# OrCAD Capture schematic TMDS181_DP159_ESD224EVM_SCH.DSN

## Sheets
1 P03:  DP159RGZ: size B; title: DP159 RGZ (48-pin QFN); rev: A.0; company: Texas Instruments, CIS/ICP; note: GAGGIA.DSN
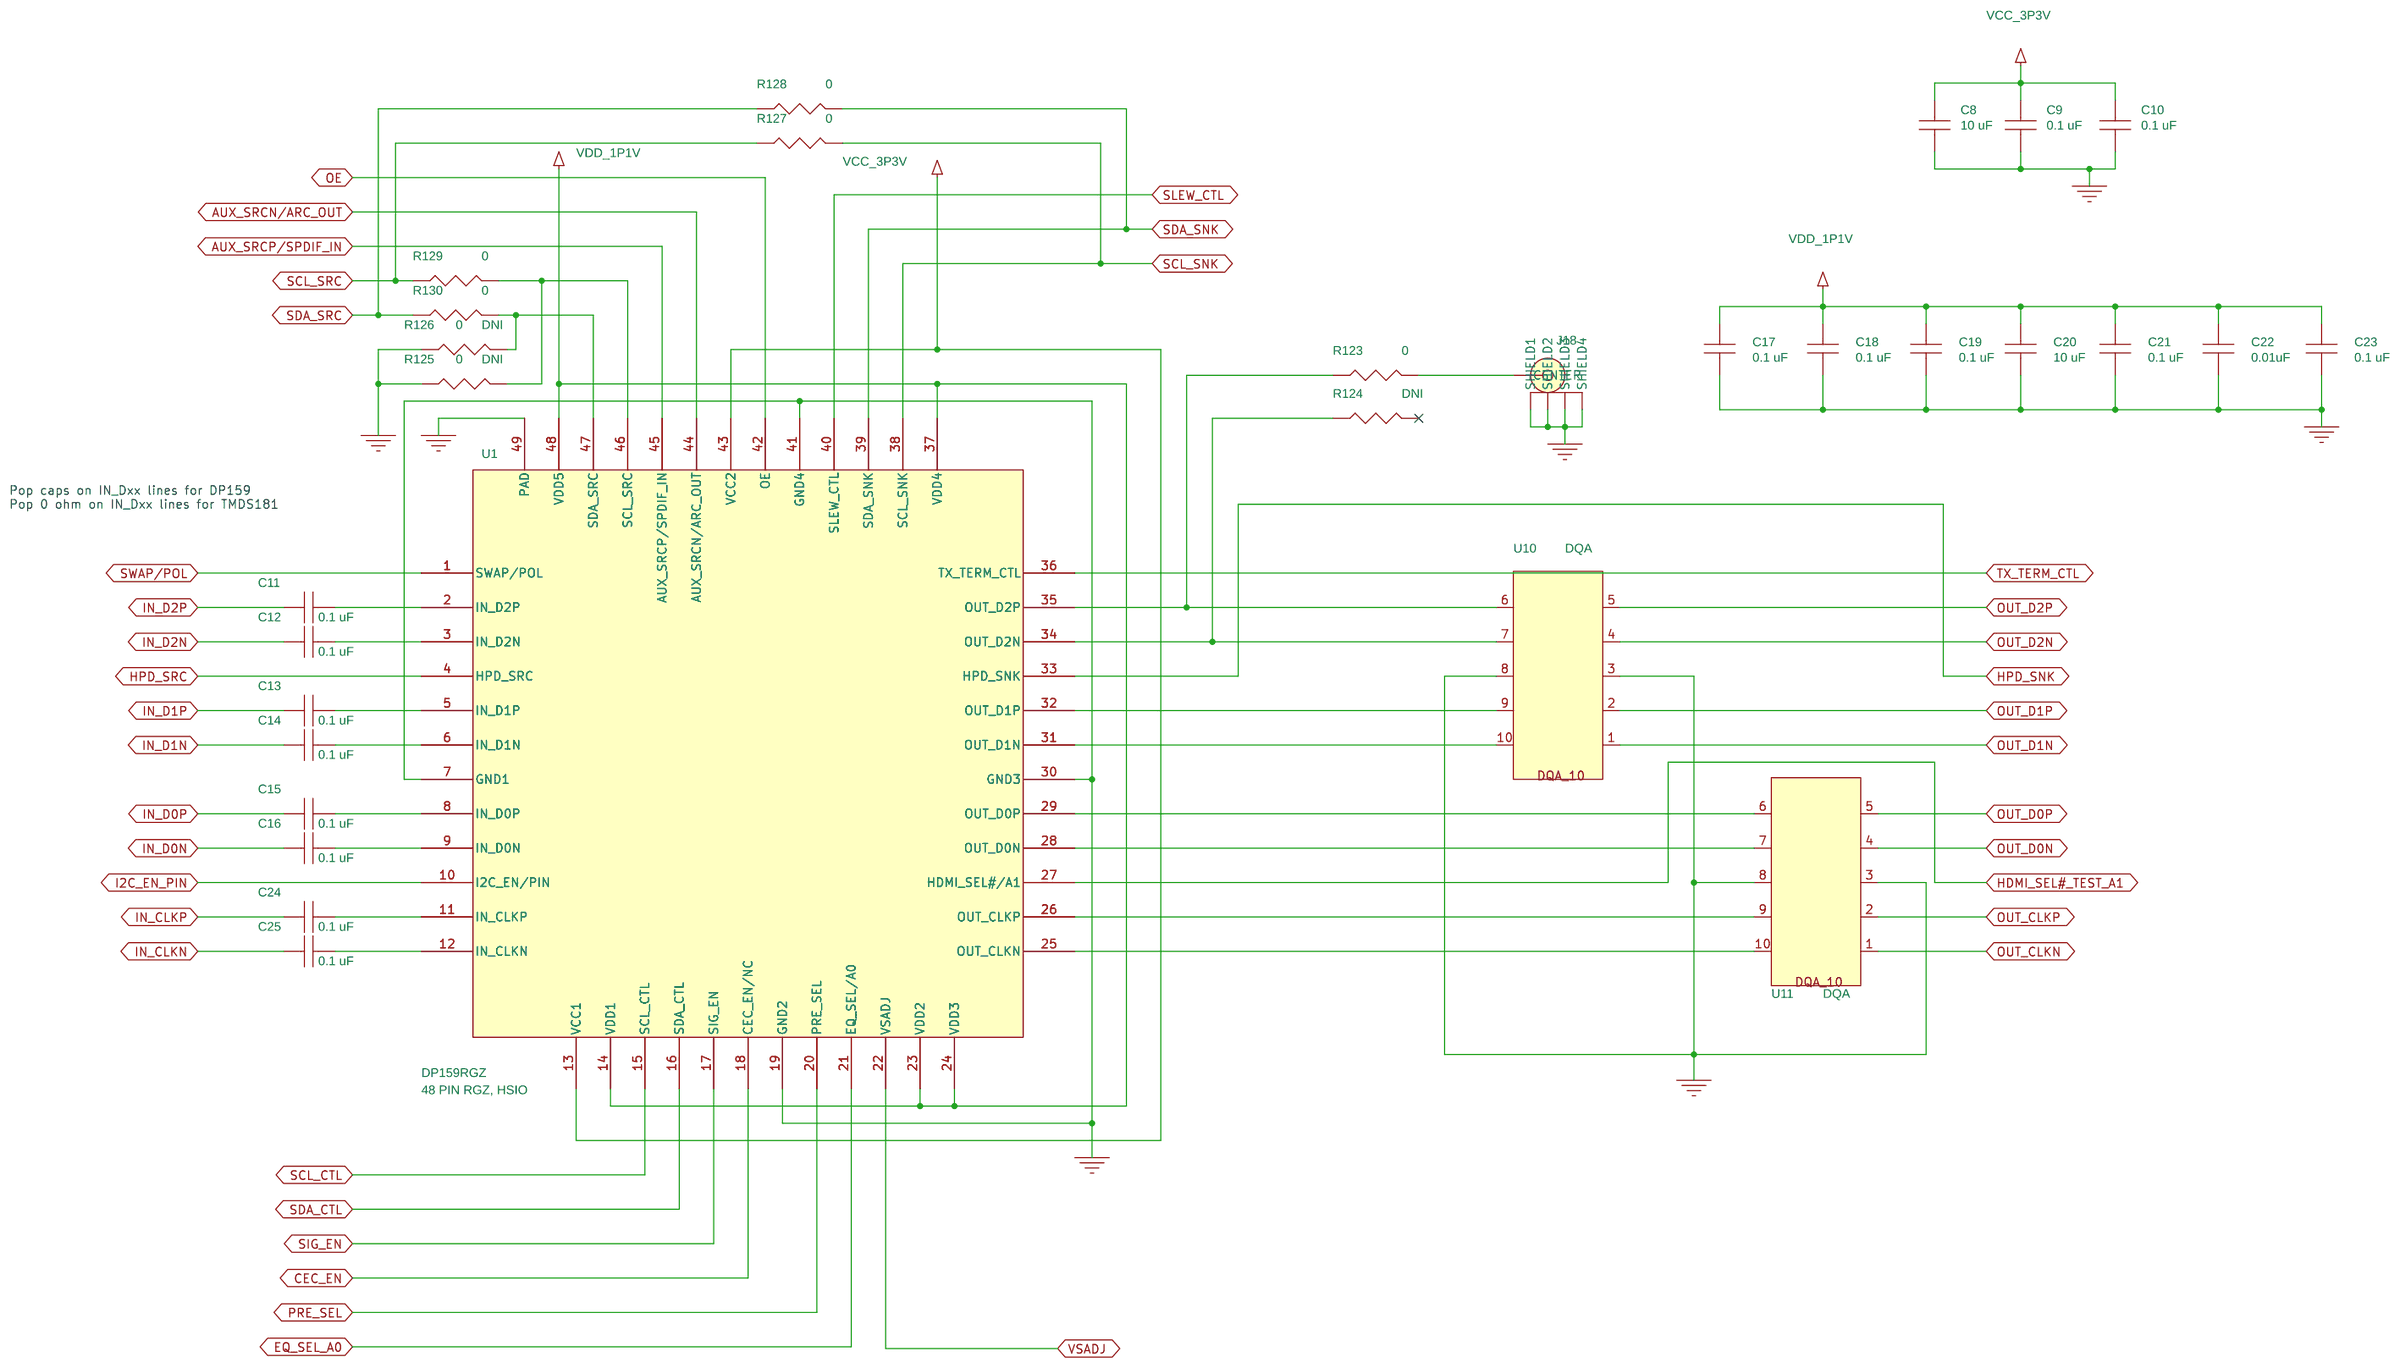
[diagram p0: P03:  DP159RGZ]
2 P06:  RESET: size A; title: RESET
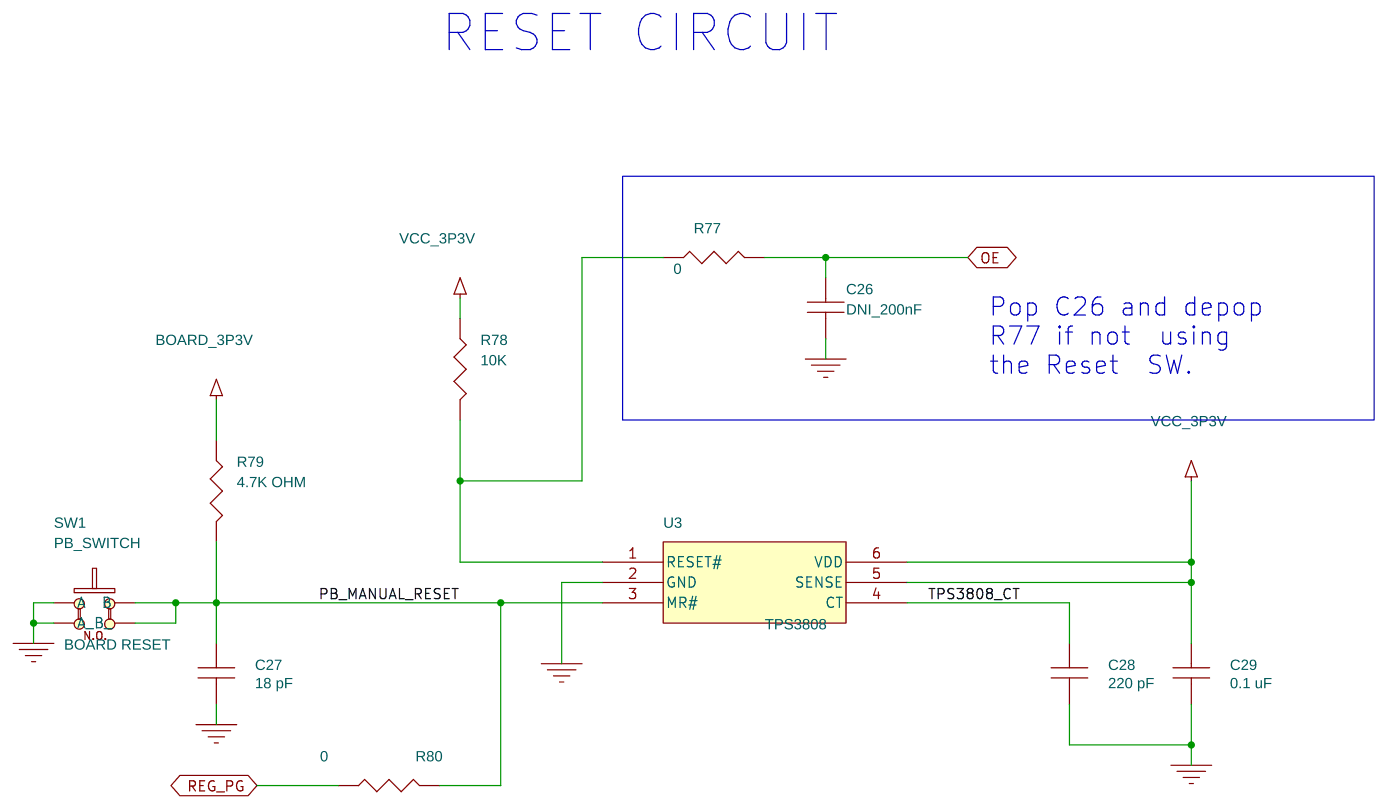
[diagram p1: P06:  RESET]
3 P01:  TITLE: size A; title: TMDS181_DP159_ESD224EVM_REVA
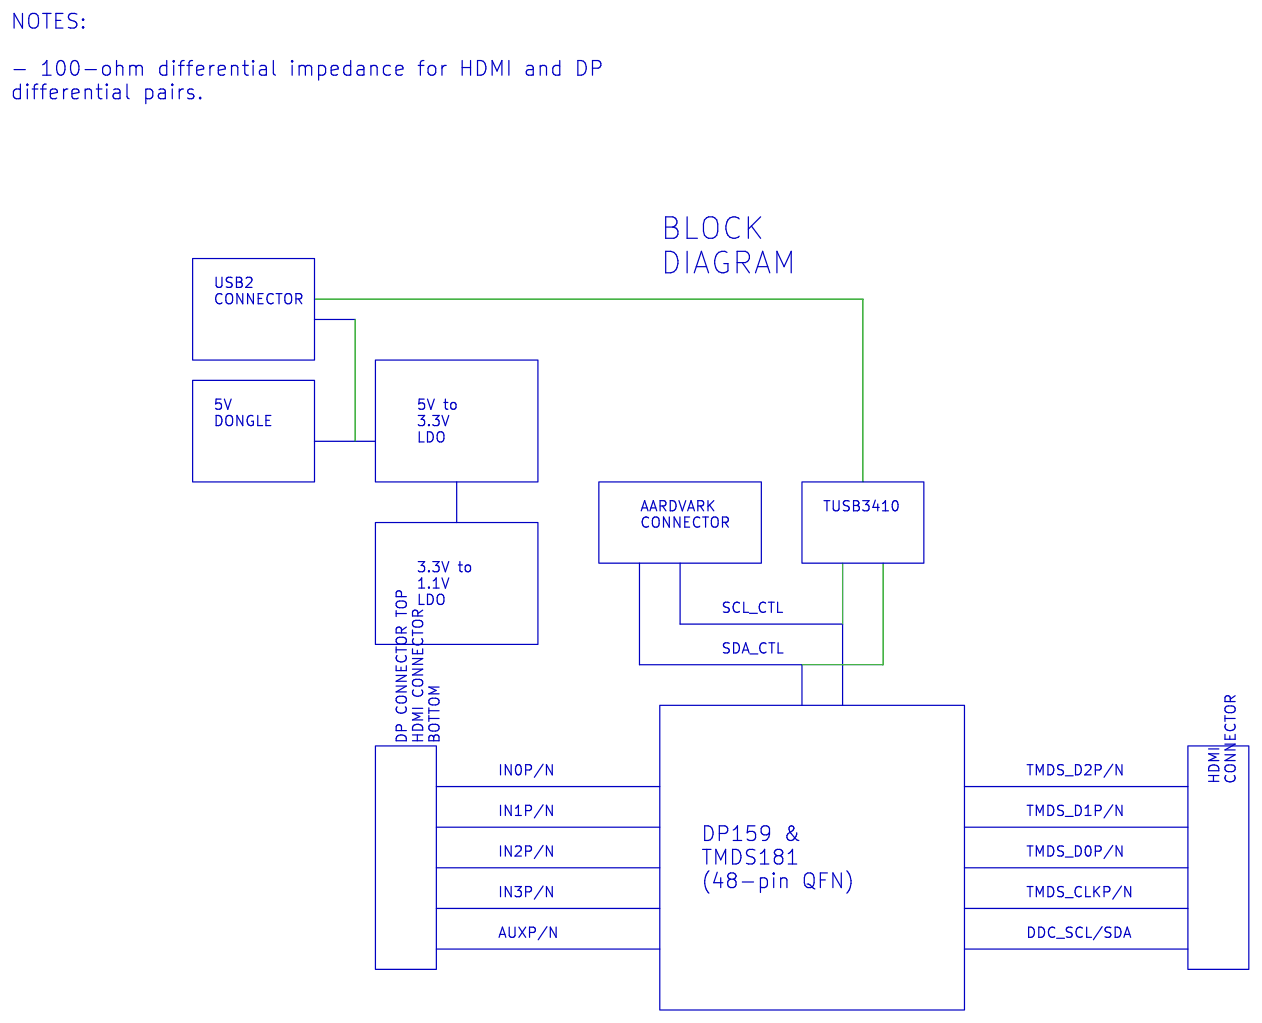
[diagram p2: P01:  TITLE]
4 P07:  POWER: size B; title: 1.1V AND 3.3V REGULATORS
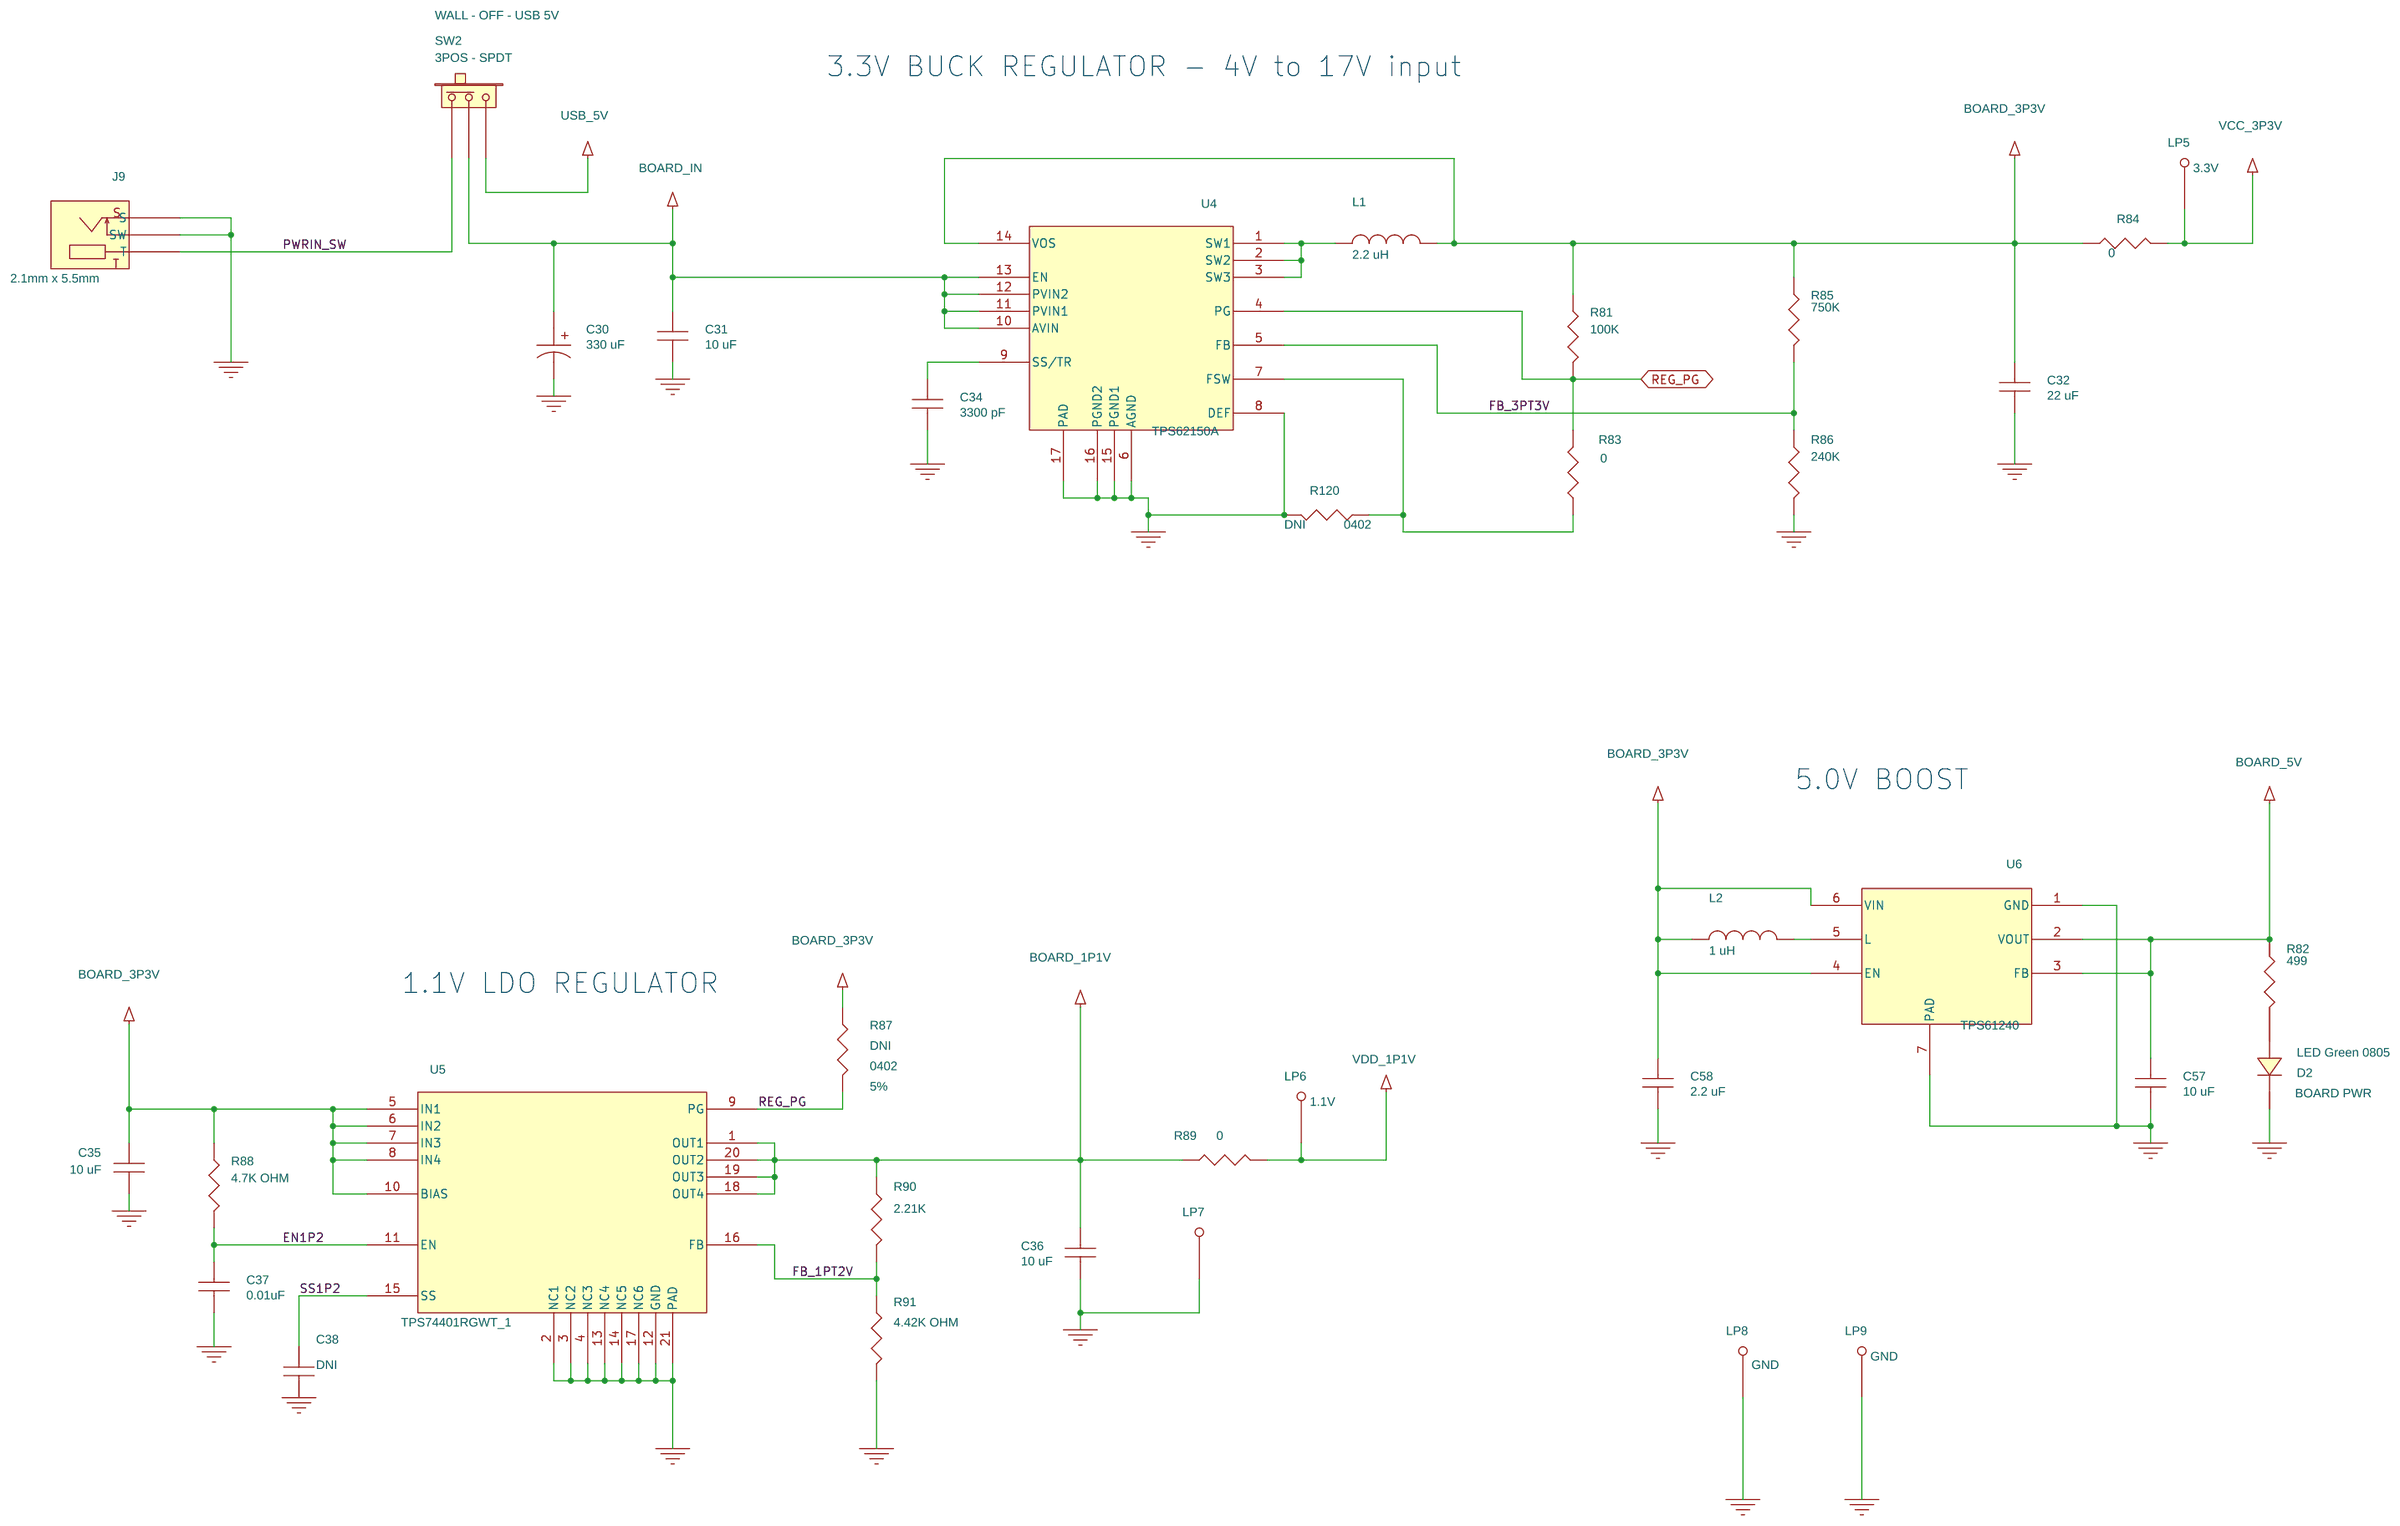
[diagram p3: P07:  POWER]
5 P04:  HDMI TX CONNECTOR: size A; title: HDMI TX CONNECTOR
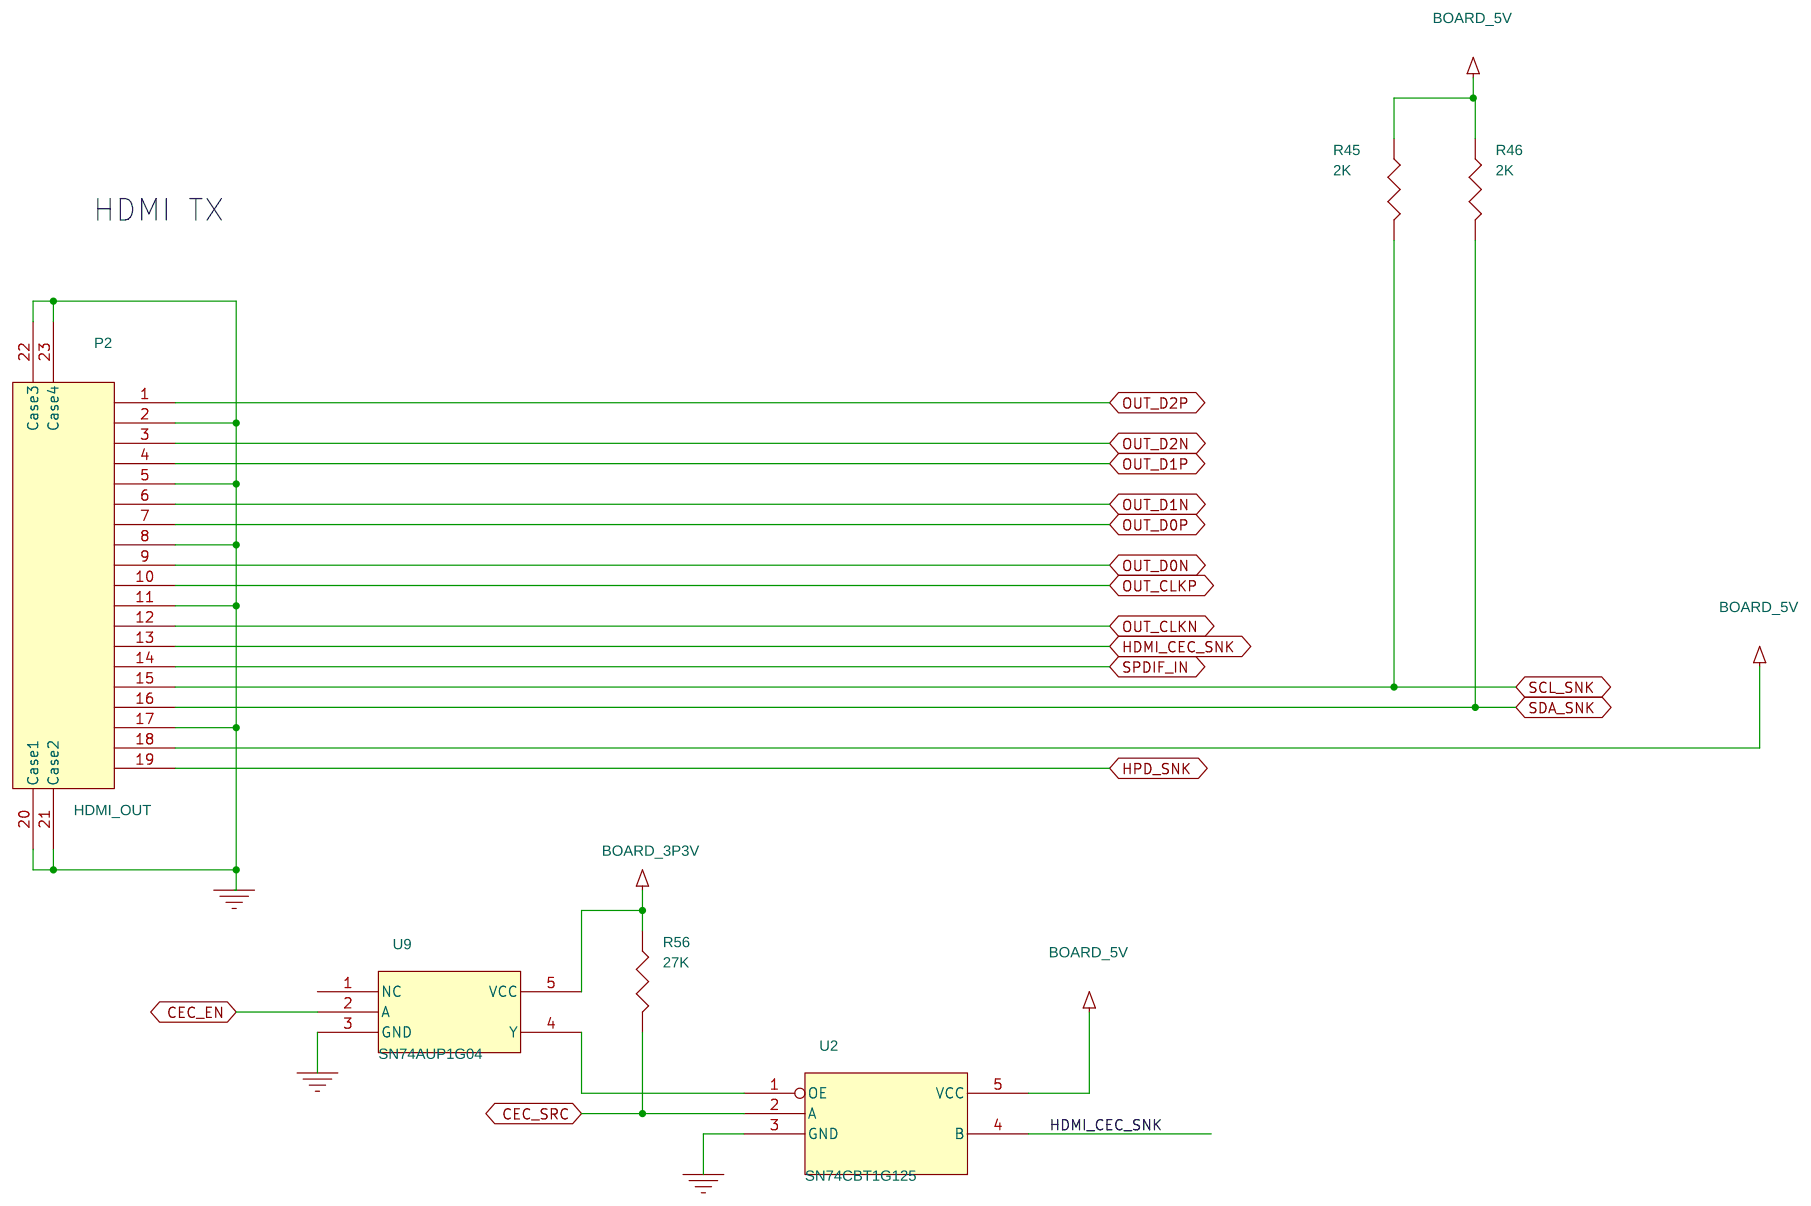
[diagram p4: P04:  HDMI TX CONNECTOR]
6 P08:  TUSB3410: size B; title: TUSB3410
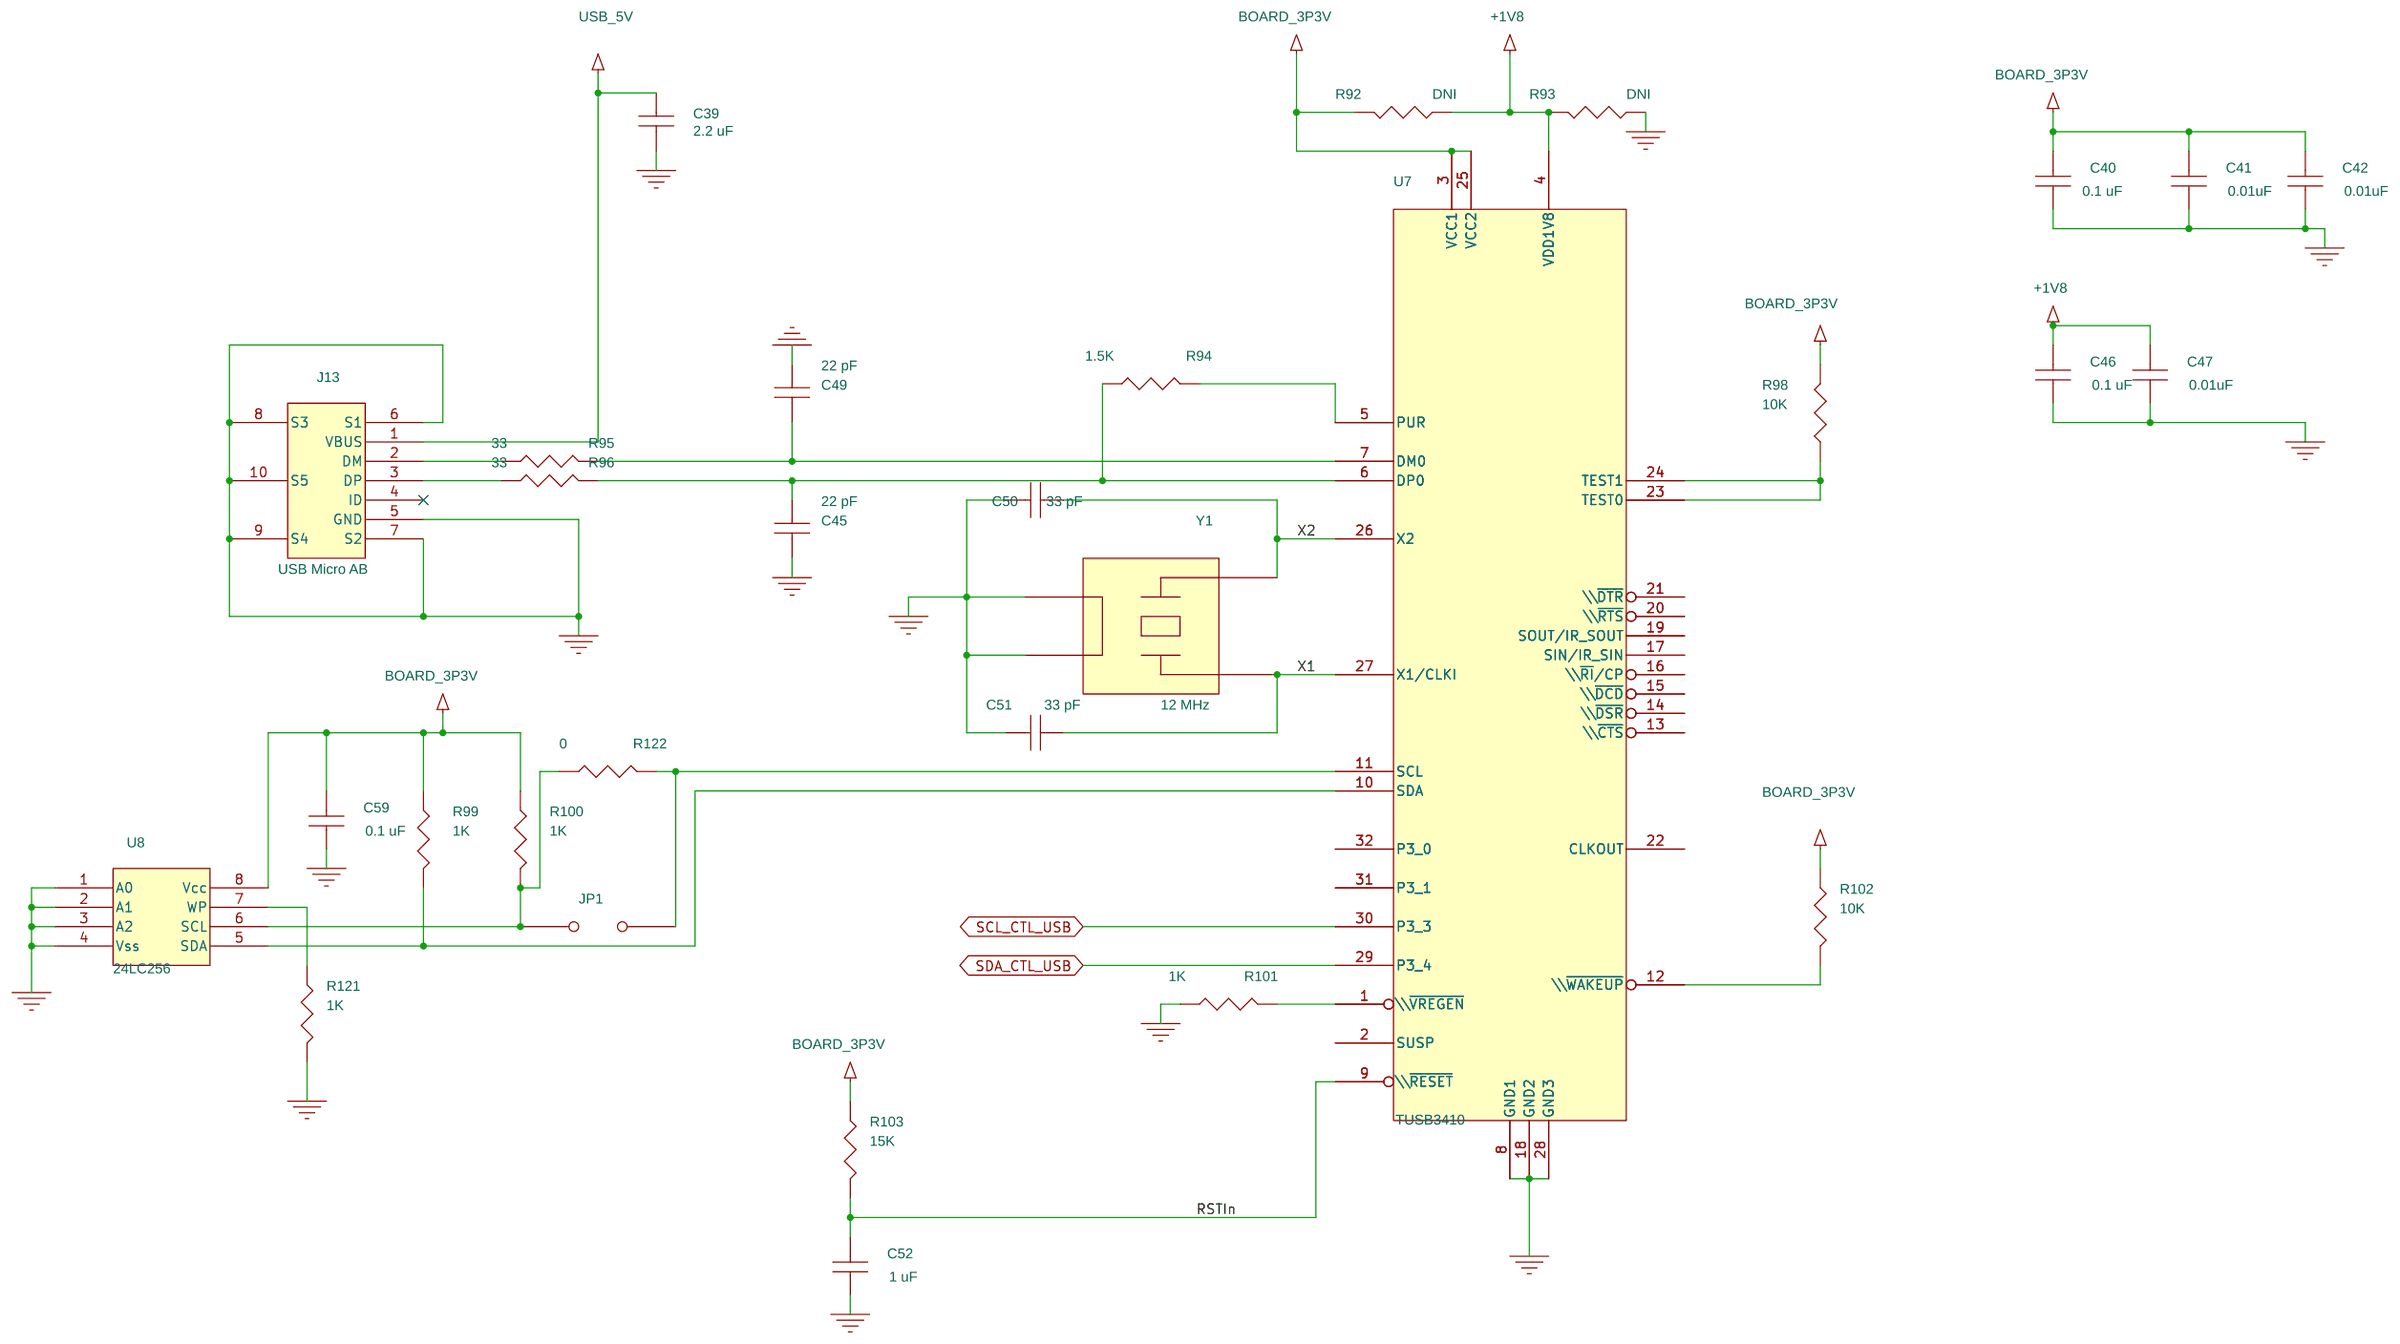
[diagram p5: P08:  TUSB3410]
7 P05:  DP159 SEL OPTIONS: size B; title: SELECT OPTIONS
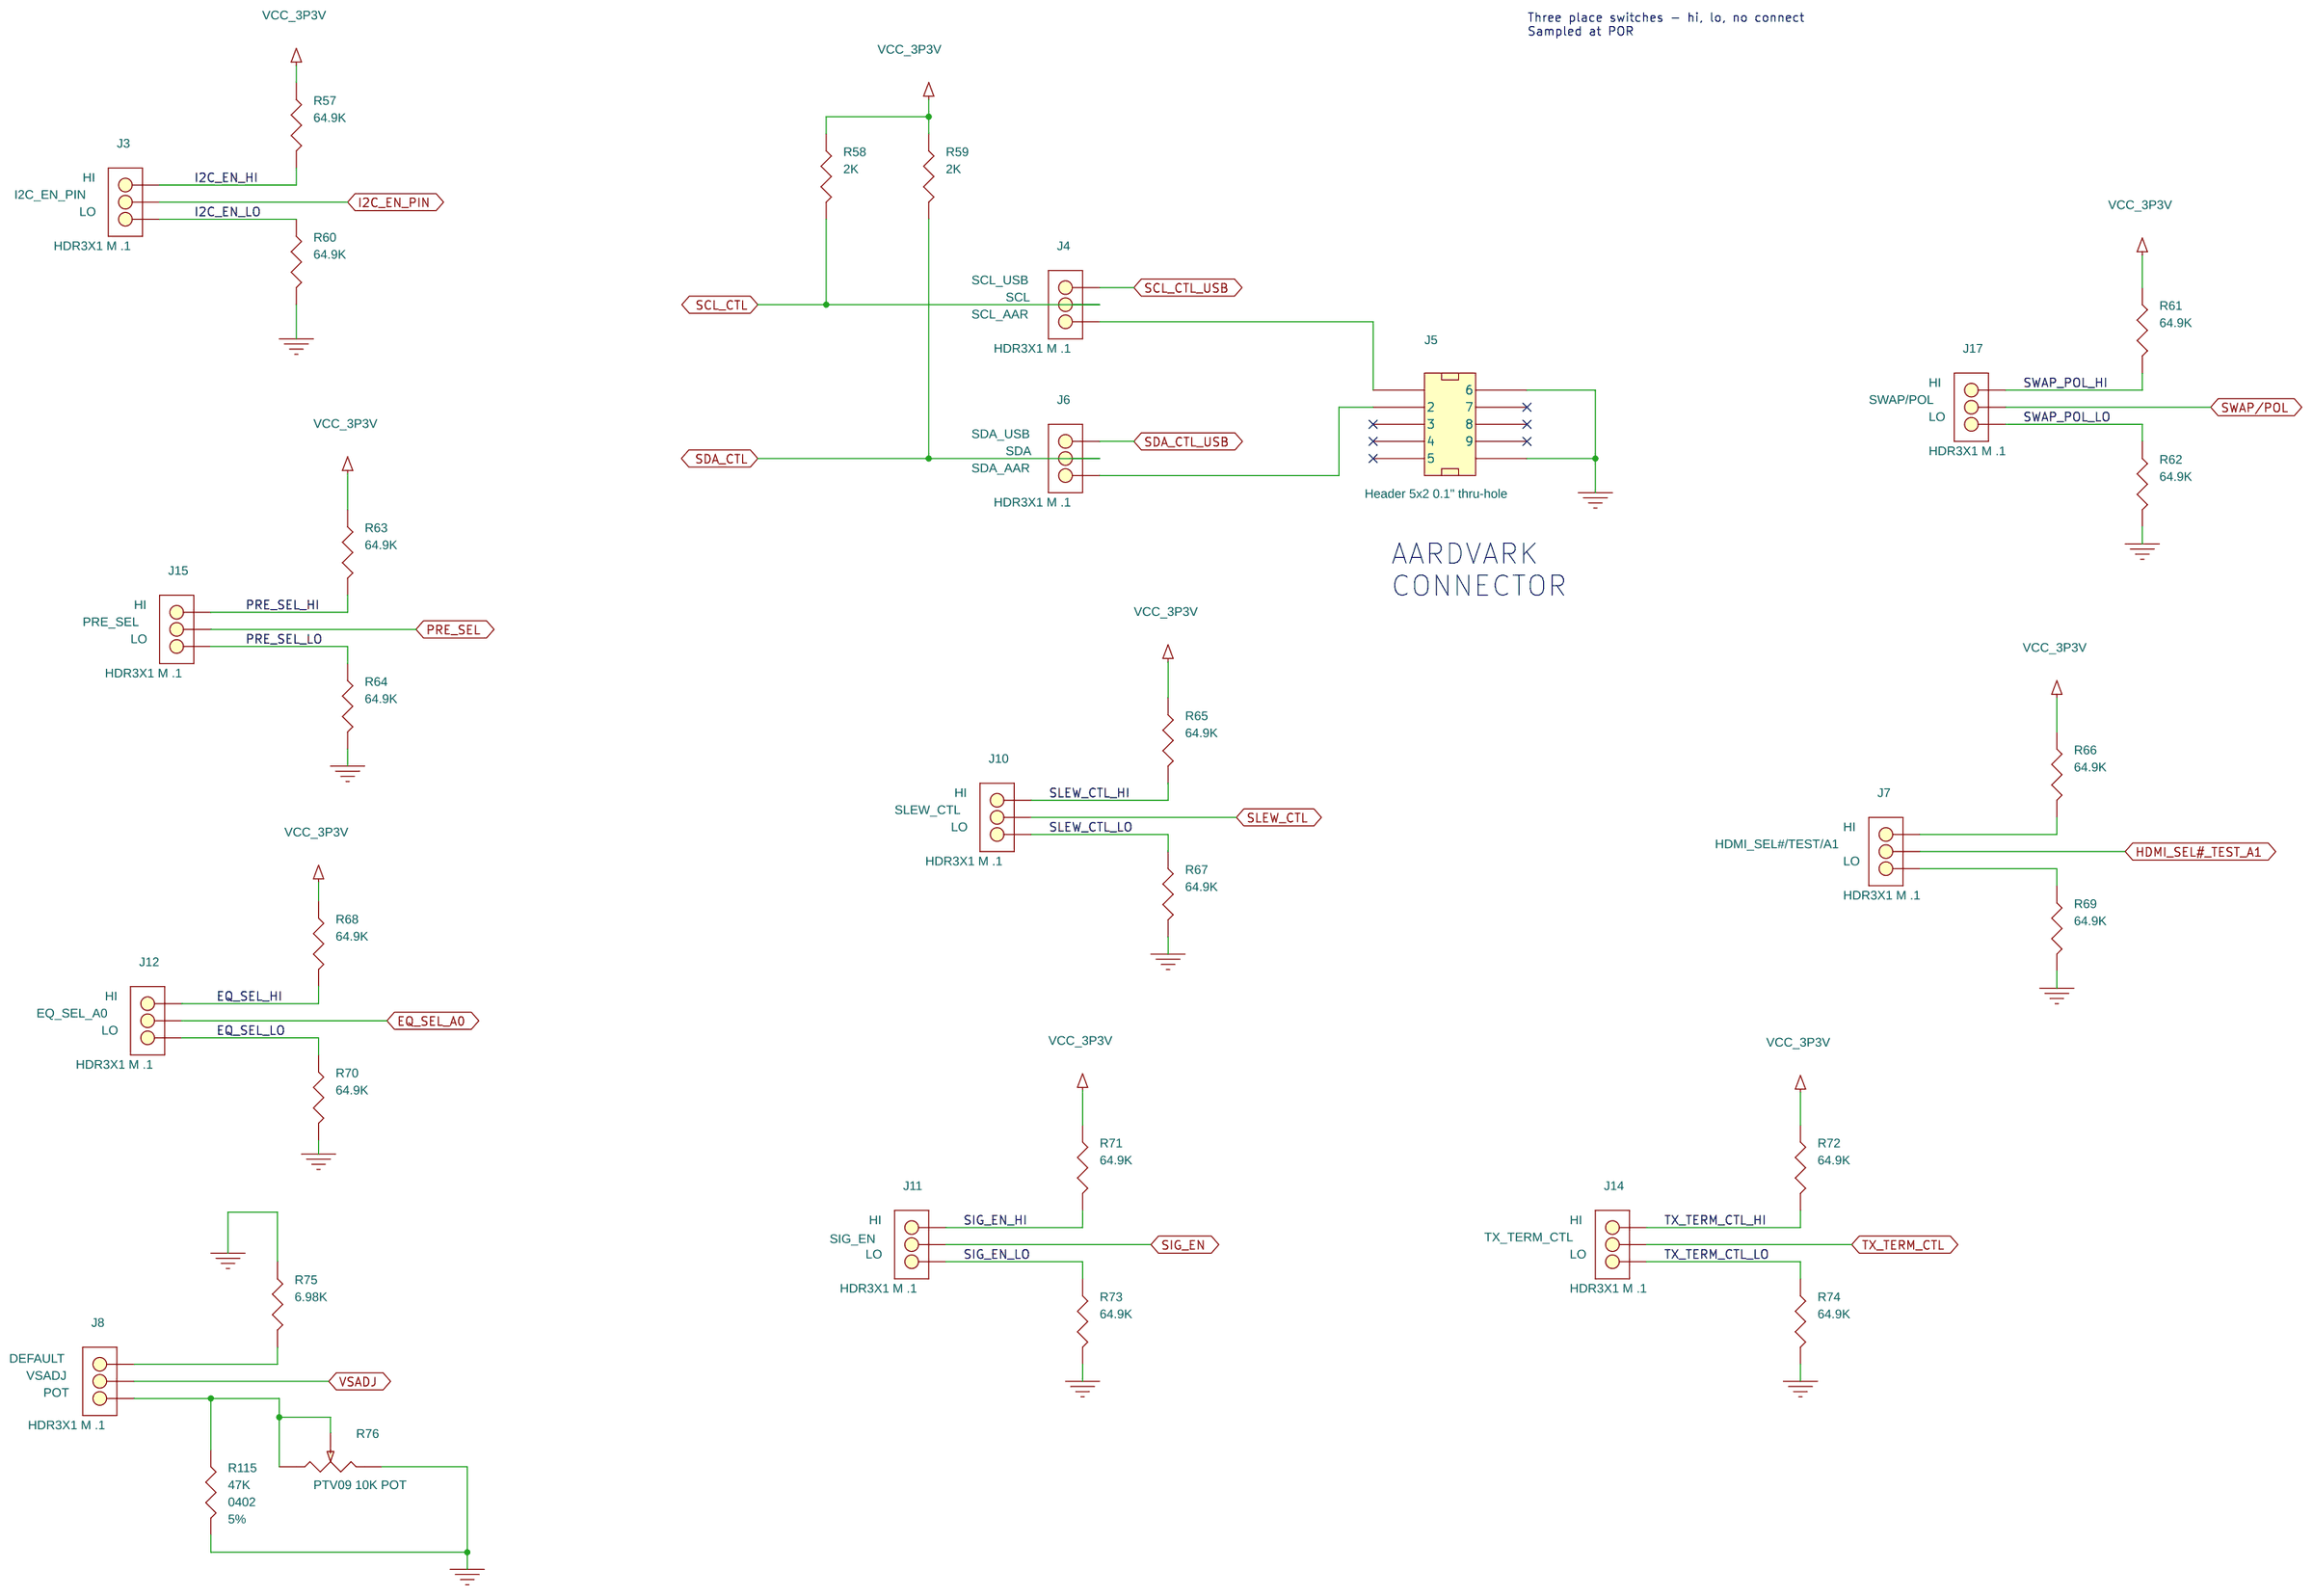
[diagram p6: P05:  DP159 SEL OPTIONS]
8 P02:  DP HDMI INPUT CONNECTORS: size B; title: DP  HDMI INPUT CONNECTORS
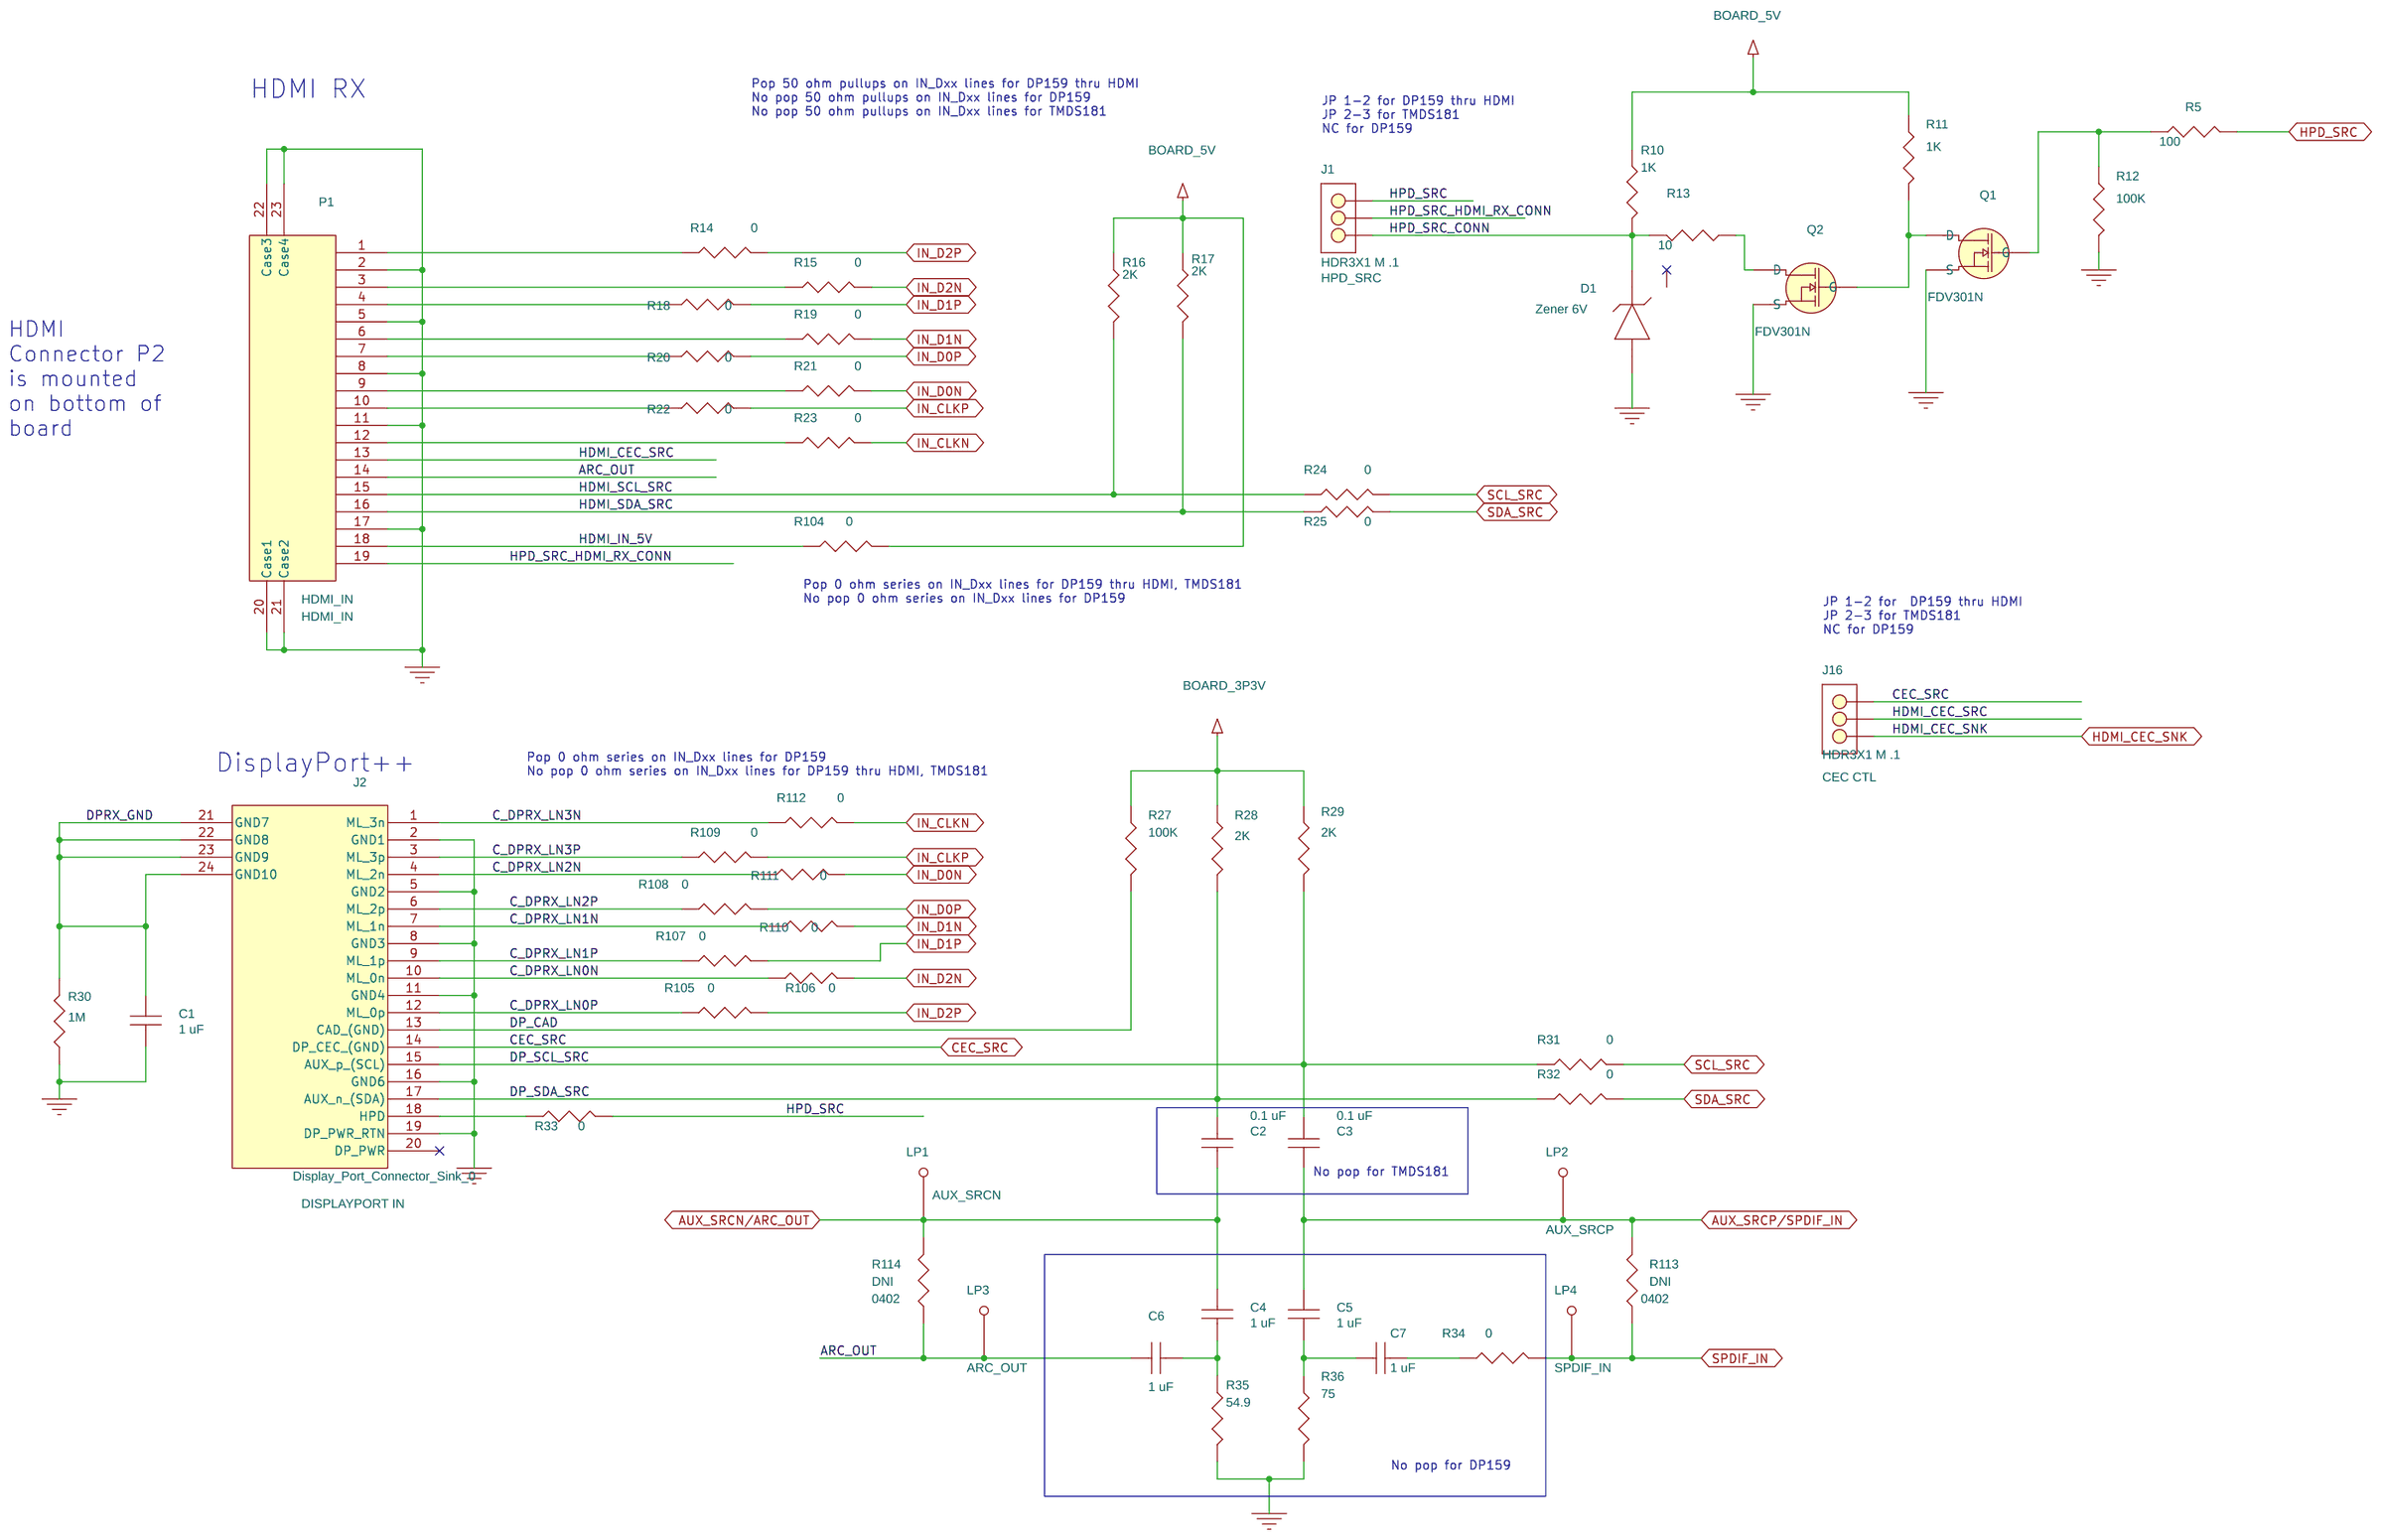
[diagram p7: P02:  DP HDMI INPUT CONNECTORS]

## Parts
sheet P02:  DP HDMI INPUT CONNECTORS
C1  1 uF  [0603]
C2  0.1 uF  [0402]
C3  0.1 uF  [0402]
C4  1 uF  [0603]
C5  1 uF  [0603]
C6  1 uF  [0603]
C7  1 uF  [0603]
D1  Zener 6V  [SOT23_3]
J1  HDR3X1 M .1  [HDR_THVT_1x3_100]
J2  Display_Port_Connector_Sink_0  [con_dp_SD-47272-001]
J16  HDR3X1 M .1  [HDR_THVT_1x3_100]
LP1  LP  [TESTLOOP]
LP2  LP  [TESTLOOP]
LP3  LP  [TESTLOOP]
LP4  LP  [TESTLOOP]
P1  HDMI_IN  [con_hdmi_SD-47151-001]
Q1  FDV301N  [SOT23_3]
Q2  FDV301N  [SOT23_3]
R5  100  [0402]
R10  1K  [0402]
R11  1K  [0402]
R12  100K  [0402]
R13  10  [0402]
R14  0  [0201]
R15  0  [0201]
R16  2K  [0402]
R17  2K  [0402]
R18  0  [0201]
R19  0  [0201]
R20  0  [0201]
R21  0  [0201]
R22  0  [0201]
R23  0  [0201]
R24  0  [0201]
R25  0  [0201]
R27  100K  [0402]
R28  2K  [0402]
R29  2K  [0402]
R30  1M  [0402]
R31  0  [0201]
R32  0  [0201]
R33  0  [0201]
R34  0  [0201]
R35  54.9  [0402]
R36  75  [0402]
R104  0  [0402]
R105  0  [0201]
R106  0  [0201]
R107  0  [0201]
R108  0  [0201]
R109  0  [0201]
R110  0  [0201]
R111  0  [0201]
R112  0  [0201]
R113  DNI  [0402]
R114  DNI  [0402]
sheet P03:  DP159RGZ
C8  10 uF  [0805]
C9  0.1 uF  [0402]
C10  0.1 uF  [0402]
C11  0.1 uF  [0201]
C12  0.1 uF  [0201]
C13  0.1 uF  [0201]
C14  0.1 uF  [0201]
C15  0.1 uF  [0201]
C16  0.1 uF  [0201]
C17  0.1 uF  [0402]
C18  0.1 uF  [0402]
C19  0.1 uF  [0402]
C20  10 uF  [0805]
C21  0.1 uF  [0402]
C22  0.01uF  [0402]
C23  0.1 uF  [0402]
C24  0.1 uF  [0201]
C25  0.1 uF  [0201]
J18  5-1814832-1  [TE_5-1814832-1]
R123  0  [0201]
R124  DNI  [0201]
R125  0  [0201]
R126  0  [0201]
R127  0  [0201]
R128  0  [0201]
R129  0  [0201]
R130  0  [0201]
U1  DP159RGZ  [rgz48_gryphics_48qfn07-0p5]
U10  DQA  [SON50P100X250X55-10]
U11  DQA  [SON50P100X250X55-10]
sheet P04:  HDMI TX CONNECTOR
P2  HDMI_OUT  [con_hdmi_SD-47151-001]
R45  2K  [0402]
R46  2K  [0402]
R56  27K  [0402]
U2  SN74CBT1G125  [DCK_r-pdso-g5]
U9  SN74AUP1G04  [DCK_r-pdso-g5]
sheet P05:  DP159 SEL OPTIONS
J3  HDR3X1 M .1  [HDR_THVT_1x3_100]
J4  HDR3X1 M .1  [HDR_THVT_1x3_100]
J5  Header 5x2 0.1" thru-hole  [con_thvt_shrd_2x5_100_m]
J6  HDR3X1 M .1  [HDR_THVT_1x3_100]
J7  HDR3X1 M .1  [HDR_THVT_1x3_100]
J8  HDR3X1 M .1  [HDR_THVT_1x3_100]
J10  HDR3X1 M .1  [HDR_THVT_1x3_100]
J11  HDR3X1 M .1  [HDR_THVT_1x3_100]
J12  HDR3X1 M .1  [HDR_THVT_1x3_100]
J14  HDR3X1 M .1  [HDR_THVT_1x3_100]
J15  HDR3X1 M .1  [HDR_THVT_1x3_100]
J17  HDR3X1 M .1  [HDR_THVT_1x3_100]
R57  64.9K  [0402]
R58  2K  [0402]
R59  2K  [0402]
R60  64.9K  [0402]
R61  64.9K  [0402]
R62  64.9K  [0402]
R63  64.9K  [0402]
R64  64.9K  [0402]
R65  64.9K  [0402]
R66  64.9K  [0402]
R67  64.9K  [0402]
R68  64.9K  [0402]
R69  64.9K  [0402]
R70  64.9K  [0402]
R71  64.9K  [0402]
R72  64.9K  [0402]
R73  64.9K  [0402]
R74  64.9K  [0402]
R75  6.98K  [0402]
R76  PTV09 10K POT  [VAR_RES_THVT_PTV09A-1_123]
R115  47K  [0402]
sheet P06:  RESET
C26  DNI_200nF  [0402]
C27  18 pF  [0402]
C28  220 pF  [0402]
C29  0.1 uF  [0402]
R77  0  [0402]
R78  10K  [0402]
R79  4.7K OHM  [0402]
R80  0  [0402]
SW1  PB_SWITCH  [SW_MOM_2NO]
U3  TPS3808  [DBV_R-PDSO-G6]
sheet P07:  POWER
C30  330 uF  [7343]
C31  10 uF  [0805]
C32  22 uF  [0805]
C34  3300 pF  [0402]
C35  10 uF  [0805]
C36  10 uF  [0805]
C37  0.01uF  [0402]
C38  DNI  [0402]
C57  10 uF  [0805]
C58  2.2 uF  [0805]
D2  LED Green 0805  [0805]
J9  2.1mm x 5.5mm  [PJ-202AH]
L1  2.2 uH  [IND_1008]
L2  1 uH  [IND_1008]
LP5  LP  [TESTLOOP]
LP6  LP  [TESTLOOP]
LP7  LP  [TESTLOOP]
LP8  LP  [TESTLOOP]
LP9  LP  [TESTLOOP]
R81  100K  [0402]
R82  499  [0402]
R83  0  [0402]
R84  0  [0402]
R85  750K  [0402]
R86  240K  [0402]
R87  DNI  [0402]
R88  4.7K OHM  [0402]
R89  0  [0402]
R90  2.21K  [0402]
R91  4.42K OHM  [0402]
R120  DNI  [0402]
SW2  3POS - SPDT  [sw_thvt_spdt_3_185p]
U4  TPS62150A  [RGT_QFN-16]
U5  TPS74401RGWT_1  [QFN_20_203x203_26]
U6  TPS61240  [DRV_S-PWSON-N6]
sheet P08:  TUSB3410
C39  2.2 uF  [0805]
C40  0.1 uF  [0402]
C41  0.01uF  [0402]
C42  0.01uF  [0402]
C45  22 pF  [0402]
C46  0.1 uF  [0402]
C47  0.01uF  [0402]
C49  22 pF  [0402]
C50  33 pF  [0402]
C51  33 pF  [0402]
C52  1 uF  [0603]
C59  0.1 uF  [0402]
J13  USB Micro AB  [usb_micro_ab_molex]
JP1  961102-6404-AR  [HDR_THVT_1x2_100]
R92  DNI  [0402]
R93  DNI  [0402]
R94  1.5K  [0402]
R95  33  [0201]
R96  33  [0201]
R98  10K  [0402]
R99  1K  [0402]
R100  1K  [0402]
R101  1K  [0402]
R102  10K  [0402]
R103  15K  [0402]
R121  1K  [0402]
R122  0  [0402]
U7  TUSB3410  [PQFP_32_7P2X7P2_P8MM]
U8  24LC256  [soic_8_197x157_50]
Y1  12 MHz  [XTAL_4_SM_126X98]

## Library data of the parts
C1 C4-C7 C52 = LMK107B7105KA-T
C2 C3 C9 C10 C17-C19 C21 C23 C29 C40 C46 C59 = CC0402KRX5R6BB104
D1 = MMBZ5233B-7-F
J1 = 961103-6404-AR: SILKTEXT: HPD_SRC
J2 = 47272-0001: SILKTEXT: DISPLAYPORT IN
J16 = 961103-6404-AR: SILKTEXT: CEC CTL
LP1 = 151-103-RC: SILKTEXT: AUX_SRCN
LP2 = 151-103-RC: SILKTEXT: AUX_SRCP
LP3 = 151-103-RC: SILKTEXT: ARC_OUT
LP4 = 151-103-RC: SILKTEXT: SPDIF_IN
P1 P2 = 47151-0001
Q1 Q2 = FDV301N
R5 = RC0402FR-07100RL
R10 R11 R99-R101 R121 = RC0402JR-071KL
R12 R27 R81 = RC0402JR-07100KL
R13 = RC0402JR-0710RL
R14 R15 R18-R25 R31-R34 R105-R112 R123 R124 R127-R130 = ERJ-1GN0R00C
R16 R17 R28 R29 R45 R46 R58 R59 = RC0402JR-072KL
R30 = RC0402FR-071ML
R35 = ERA-2AEB54R9X
R36 = RC0402JR-0775RL
R77 R80 R83 R84 R89 R104 R122 = ERJ-2GE0R00X
R87 R92 R93 R113 R114 = R: Tolerance: 5%
C8 C20 C31 C35 C36 C57 = C2012X5R1E106K125AB
C11-C16 C24 C25 = GRM033R61E104KE14J
C22 C37 C41 C42 C47 = GRM155R71H103JA88D
J18 = 5-1814832-1
R125 R126 = ERJ-1GN0R00C: REMARKS: DNI
U1 = DP159RGZ_6: IC RETIMER DVI HDMI 6GBPS 48VQFN; MANUFACTURER: TEXAS INSTRUMENTS; PACK_TYPE: 48_RGZ; PART_NUMBER: TMDS181RGZR; SILKTEXT: 48 PIN RGZ, HSIO
U10 U11 = DQA
R56 = ERA-2AEB273X
U2 = SN74CBT1G125
U9 = SN74AUP1G04
J3 = 961103-6404-AR: SILKTEXT1: HI; SILKTEXT2: I2C_EN_PIN; SILKTEXT3: LO
J4 = 961103-6404-AR: SILKTEXT1: SCL_USB; SILKTEXT2: SCL; SILKTEXT3: SCL_AAR
J5 = N2510-6002-RB
J6 = 961103-6404-AR: SILKTEXT1: SDA_USB; SILKTEXT2: SDA; SILKTEXT3: SDA_AAR
J7 = 961103-6404-AR: SILKTEXT1: HI; SILKTEXT2: HDMI_SEL#/TEST/A1; SILKTEXT3: LO
J8 = 961103-6404-AR: SILKTEXT1: DEFAULT; SILKTEXT2: VSADJ; SILKTEXT3: POT
J10 = 961103-6404-AR: SILKTEXT1: HI; SILKTEXT2: SLEW_CTL; SILKTEXT3: LO
J11 = 961103-6404-AR: SILKTEXT1: HI; SILKTEXT2: SIG_EN; SILKTEXT3: LO
J12 = 961103-6404-AR: SILKTEXT1: HI; SILKTEXT2: EQ_SEL_A0; SILKTEXT3: LO
J14 = 961103-6404-AR: SILKTEXT1: HI; SILKTEXT2: TX_TERM_CTL; SILKTEXT3: LO
J15 = 961103-6404-AR: SILKTEXT1: HI; SILKTEXT2: PRE_SEL; SILKTEXT3: LO
J17 = 961103-6404-AR: SILKTEXT1: HI; SILKTEXT2: SWAP/POL; SILKTEXT3: LO
R57 R60-R74 = RC0402FR-0764K9L
R75 = ERA-2AEB6981X
R76 = POT
R115 = ERA-2APB473X: Tolerance: 5%
C26 = LMK105BJ224KV-F
C27 = 04025A180JAT2A
C28 = UMK105B7221KV-F
R78 R98 R102 = RC0402JR-0710KL
R79 R88 = RC0402JR-074K7L
SW1 = PB_SWITCH_0: SILKTEXT: BOARD RESET
U3 = TPS3808DBV
C30 = T495X337K010ATE060: MANUFACTURER: KEMET
C32 = C0805C226K9PAC7800
C34 = CL05B332KB5NNNC
C38 = CAP_NP
C39 C58 = EMK212BJ225KG-T
D2 = LTST-C171GKT: SILKTEXT: BOARD PWR
J9 = BNC_2
L1 = VLS252010ET-2R2M
L2 = NLCV25T-1R0M-EFR
LP5 = 151-103-RC: SILKTEXT: 3.3V
LP6 = 151-103-RC: SILKTEXT: 1.1V
LP7 = 151-103-RC
LP8 LP9 = 151-103-RC: SILKTEXT: GND
R82 = CRCW0402499RDHEDP
R85 = CRCW0402750KJNED
R86 = CRCW0402240KJNED
R90 = ERA-2APB2211X: RES,THICK FILM,2.21 KOHM,0.1%,0.063W,0402
R91 = RMCF0402FT4K42
R120 = R: Tolerance: 1%
SW2 = SW_SLIDE_SPDT2: SILKTEXT: WALL - OFF - USB 5V
U4 = TPS62150A
U5 = TPS74401RGWT_1
U6 = TPS61420
C45 C49 = GRM1555C1H220JA01D
C50 C51 = GRM1555C1H330JA01D
J13 = 47590-0001
JP1 = 961102-6404-AR
R94 = RC0402JR-071K5L
R95 R96 = RC0201JR-0733RL
R103 = RC0402JR-0715KL
U7 = TUSB3410_3
U8 = I2C_0: PART_NUMBER: CAT24C256WI-GT3
Y1 = CRYSTAL14_0

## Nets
+1V8: C46.2 C47.2 R92.1 R93.2 U7.4(VDD1V8)
GND: C1.2 C8.2 C9.2 C10.2 C17.2 C18.2 C19.2 C20.2 C21.2 C22.2 C23.2 C26.2 C27.2 C28.2 C29.2 C30.2 C31.2 C32.2 C34.2 C35.2 C36.2 C37.2 C38.2 C39.2 C40.1 C41.1 C42.1 C45.2 C46.1 C47.1 C49.1 C50.2 C51.2 C52.1 C57.2 C58.2 C59.1 D1.1 D2.2(K) J2.2(GND1) J2.5(GND2) J2.8(GND3) J2.11(GND4) J2.16(GND6) J2.19(DP_PWR_RTN) J5.2(6) J5.10 J9.2(S) J9.3(SW) J13.5(GND) J13.6(S1) J13.7(S2) J13.8(S3) J13.9(S4) J13.10(S5) J18.2(SHIELD1) J18.3(SHIELD2) J18.4(SHIELD3) J18.5(SHIELD4) LP7.1 LP8.1 LP9.1 P1.2 P1.5 P1.8 P1.11 P1.17 P1.20(Case1) P1.21(Case2) P1.22(Case3) P1.23(Case4) P2.2 P2.5 P2.8 P2.11 P2.17 P2.20(Case1) P2.21(Case2) P2.22(Case3) P2.23(Case4) Q1.2(S) Q2.2(S) R12.1 R30.1 R35.1 R36.1 R60.2 R62.2 R64.2 R67.2 R69.2 R70.2 R73.2 R74.2 R75.1 R76.3(B) R86.1 R91.1 R93.1 R101.2 R115.2 R120.2 R121.2 R125.2 R126.2 SW1.1(A) SW1.2(A_) U1.7(GND1) U1.19(GND2) U1.30(GND3) U1.41(GND4) U1.49(PAD) U2.3(GND) U3.2(GND) U4.6(AGND) U4.8(DEF) U4.15(PGND1) U4.16(PGND2) U4.17(PAD) U5.2(NC1) U5.3(NC2) U5.4(NC3) U5.12(GND) U5.13(NC4) U5.14(NC5) U5.17(NC6) U5.21(PAD) U6.1(GND) U6.7(PAD) U7.8(GND1) U7.18(GND2) U7.28(GND3) U8.1(A0) U8.2(A1) U8.3(A2) U8.4(Vss) U9.3(GND) U10.3 U10.8 U11.3 U11.8 Y1.2 Y1.4
VCC_3P3V: C8.1 C9.1 C10.1 C29.1 LP5.1 R57.1 R58.1 R59.1 R61.1 R63.1 R65.1 R66.1 R68.1 R71.1 R72.1 R78.1 R84.1 U1.13(VCC1) U1.43(VCC2) U3.5(SENSE) U3.6(VDD)
VDD_1P1V: C17.1 C18.1 C19.1 C20.1 C21.1 C22.1 C23.1 LP6.1 R89.1 U1.14(VDD1) U1.23(VDD2) U1.24(VDD3) U1.37(VDD4) U1.48(VDD5)
ARC_OUT: C6.1 LP3.1 P1.14 R114.1
AUX_SRCN/ARC_OUT: C2.1 C4.1 LP1.1 R114.2 U1.44(AUX_SRCN/ARC_OUT)
AUX_SRCP/SPDIF_IN: C3.1 C5.1 LP2.1 R113.2 U1.45(AUX_SRCP/SPDIF_IN)
BOARD_1P1V: C36.1 R89.2 R90.2 U5.1(OUT1) U5.18(OUT4) U5.19(OUT3) U5.20(OUT2)
BOARD_3P3V: C32.1 C35.1 C40.2 C41.2 C42.2 C58.1 C59.2 L1.2 L2.1 R27.2 R28.2 R29.2 R56.2 R79.1 R81.1 R84.2 R85.2 R87.1 R88.1 R92.2 R98.1 R99.1 R100.1 R102.1 R103.1 U4.14(VOS) U5.5(IN1) U5.6(IN2) U5.7(IN3) U5.8(IN4) U5.10(BIAS) U6.4(EN) U6.6(VIN) U7.3(VCC1) U7.25(VCC2) U8.8(Vcc) U9.5(VCC)
BOARD_5V: C57.1 P2.18 R10.2 R11.2 R16.2 R17.2 R45.2 R46.2 R82.2 R104.1 U2.5(VCC) U6.2(VOUT) U6.3(FB)
BOARD_IN: C30.1 C31.1 SW2.2 U4.10(AVIN) U4.11(PVIN1) U4.12(PVIN2) U4.13(EN)
C_DPRX_LN0N: J2.10(ML_0n) R106.2
C_DPRX_LN0P: J2.12(ML_0p) R105.2
C_DPRX_LN1N: J2.7(ML_1n) R110.2
C_DPRX_LN1P: J2.9(ML_1p) R107.2
C_DPRX_LN2N: J2.4(ML_2n) R111.2
C_DPRX_LN2P: J2.6(ML_2p) R108.2
C_DPRX_LN3N: J2.1(ML_3n) R112.2
C_DPRX_LN3P: J2.3(ML_3p) R109.2
CEC_EN: U1.18(CEC_EN/NC) U9.2(A)
CEC_SRC: J2.14(DP_CEC_(GND)) J16.1 R56.1 U2.2(A)
DP_CAD: J2.13(CAD_(GND)) R27.1
DP_SCL_SRC: C3.2 J2.15(AUX_p_(SCL)) R29.1 R31.2
DP_SDA_SRC: C2.2 J2.17(AUX_n_(SDA)) R28.1 R32.2
DPRX_GND: C1.1 J2.21(GND7) J2.22(GND8) J2.23(GND9) J2.24(GND10) R30.2
EN1P2: C37.1 R88.2 U5.11(EN)
EQ_SEL_A0: J12.2 U1.21(EQ_SEL/A0)
EQ_SEL_HI: J12.1 R68.2
EQ_SEL_LO: J12.3 R70.1
FB_1PT2V: R90.1 R91.2 U5.16(FB)
FB_3PT3V: R85.1 R86.2 U4.5(FB)
HDMI_CEC_SNK: J16.3 P2.13 U2.4(B)
HDMI_CEC_SRC: J16.2 P1.13
HDMI_IN_5V: P1.18 R104.2
HDMI_SCL_SRC: P1.15 R16.1 R24.2
HDMI_SDA_SRC: P1.16 R17.1 R25.2
HDMI_SEL#_TEST_A1: J7.2 U1.27(HDMI_SEL#/A1)
HPD_SNK: P2.19 U1.33(HPD_SNK)
HPD_SRC: J1.1 R5.1 R33.1 U1.4(HPD_SRC)
HPD_SRC_CONN: D1.3 J1.3 R10.1 R13.2
HPD_SRC_HDMI_RX_CONN: J1.2 P1.19
I2C_EN_HI: J3.1 R57.2
I2C_EN_LO: J3.3 R60.1
I2C_EN_PIN: J3.2 U1.10(I2C_EN/PIN)
IN_CLKN: C25.1 R23.1 R112.1
IN_CLKP: C24.1 R22.1 R109.1
IN_D0N: C16.1 R21.1 R111.1
IN_D0P: C15.1 R20.1 R108.1
IN_D1N: C14.1 R19.1 R110.1
IN_D1P: C13.1 R18.1 R107.1
IN_D2N: C12.1 R15.1 R106.1
IN_D2P: C11.1 R14.1 R105.1
OE: C26.1 R77.1 U1.42(OE)
OUT_CLKN: P2.12 U11.1
OUT_CLKP: P2.10 U11.2
OUT_D0N: P2.9 U11.4
OUT_D0P: P2.7 U11.5
OUT_D1N: P2.6 U10.1
OUT_D1P: P2.4 U10.2
OUT_D2N: P2.3 U10.4
OUT_D2P: P2.1 U10.5
PB_MANUAL_RESET: C27.1 R79.2 R80.1 SW1.3(B_) SW1.4(B) U3.3(MR#)
PRE_SEL: J15.2 U1.20(PRE_SEL)
PRE_SEL_HI: J15.1 R63.2
PRE_SEL_LO: J15.3 R64.1
PWRIN_SW: J9.1(T) SW2.1
REG_PG: R80.2 R81.2 R83.2 R87.2 U4.4(PG) U5.9(PG)
RSTIn: C52.2 R103.2 U7.9(\\~{RESET})
SCL_CTL: J4.2 R58.2 U1.15(SCL_CTL)
SCL_CTL_USB: J4.1 U7.30(P3_3)
SCL_SNK: P2.15 R45.1 R127.1 U1.38(SCL_SNK)
SCL_SRC: R24.1 R31.1 R127.2 R129.2
SDA_CTL: J6.2 R59.2 U1.16(SDA_CTL)
SDA_CTL_USB: J6.1 U7.29(P3_4)
SDA_SNK: P2.16 R46.1 R128.1 U1.39(SDA_SNK)
SDA_SRC: R25.1 R32.1 R128.2 R130.2
SIG_EN: J11.2 U1.17(SIG_EN)
SIG_EN_HI: J11.1 R71.2
SIG_EN_LO: J11.3 R73.1
SLEW_CTL: J10.2 U1.40(SLEW_CTL)
SLEW_CTL_HI: J10.1 R65.2
SLEW_CTL_LO: J10.3 R67.1
SPDIF_IN: LP4.1 P2.14 R34.1 R113.1
SS1P2: C38.1 U5.15(SS)
SWAP/POL: J17.2 U1.1(SWAP/POL)
SWAP_POL_HI: J17.1 R61.2
SWAP_POL_LO: J17.3 R62.1
TPS3808_CT: C28.1 U3.4(CT)
TX_TERM_CTL: J14.2 U1.36(TX_TERM_CTL)
TX_TERM_CTL_HI: J14.1 R72.2
TX_TERM_CTL_LO: J14.3 R74.1
USB_5V: C39.1 J13.1(VBUS) SW2.3
VSADJ: J8.2 U1.22(VSADJ)
X1: C51.1 U7.27(X1/CLKI) Y1.3
X2: C50.1 U7.26(X2) Y1.1
N16782838: R77.2 R78.2 U3.1(RESET#)
N16869116: R125.1 R129.1 U1.46(SCL_SRC)
N16869122: R126.1 R130.1 U1.47(SDA_SRC)
N16874758: J7.1 R66.2
N16874763: J7.3 R69.1
N16880319: P1.1 R14.2
N16880326: P1.3 R15.2
N16880333: P1.4 R18.2
N16880340: P1.6 R19.2
N16880347: P1.7 R20.2
N16880354: P1.9 R21.2
N16880361: P1.10 R22.2
N16880368: P1.12 R23.2
N16881139: J5.3(2) J6.3
N16881148: J4.3 J5.1
N16883754: J8.1 R75.2
N16883759: J8.3 R76.1(A) R76.2(WIPER) R115.1
N16887406: R102.2 U7.12(\\~{WAKEUP})
N16887471: J13.3(DP) R96.2
N16892757: Q1.1(G) R5.2 R12.2
N16892765: Q1.3(D) Q2.1(G) R11.1
N16892877: Q2.3(D) R13.1
N16906083: C5.2 C7.1 R36.2
N16910161: C4.2 C6.2 R35.2
N16913511: J13.2(DM) R95.2
N16916452: JP1.1 R122.1 U7.11(SCL)
N16916458: JP1.2 R100.2 R122.2 U8.6(SCL)
N16916991: R99.2 U7.10(SDA) U8.5(SDA)
N16919313: R94.1 U7.5(PUR)
N16919318: C45.1 R94.2 R96.1 U7.6(DP0)
N16919400: C49.2 R95.1 U7.7(DM0)
N16919998: R101.1 U7.1(\\~{VREGEN})
N16925972: C11.2 U1.2(IN_D2P)
N16925975: C12.2 U1.3(IN_D2N)
N16925996: C25.2 U1.12(IN_CLKN)
N16925999: C24.2 U1.11(IN_CLKP)
N16926002: C16.2 U1.9(IN_D0N)
N16926005: C15.2 U1.8(IN_D0P)
N16926008: C14.2 U1.6(IN_D1N)
N16926011: C13.2 U1.5(IN_D1P)
N16928798: J2.18(HPD) R33.2
N16928867: C7.2 R34.2
N16961958: U2.1(OE) U9.4(Y)
N16962991: L2.2 U6.5(L)
N16965307: R83.1 R120.1 U4.7(FSW)
N16965311: L1.1 U4.1(SW1) U4.2(SW2) U4.3(SW3)
N16965335: C34.1 U4.9(SS/TR)
N16968702: R98.2 U7.23(TEST0) U7.24(TEST1)
N16982334: R121.1 U8.7(WP)
N17009590: J18.1(CENTER) R123.1
N17009600: R123.2 U1.35(OUT_D2P) U10.6
N17009604: R124.2 U1.34(OUT_D2N) U10.7
N17009633: U1.28(OUT_D0N) U11.7
N17009635: U1.29(OUT_D0P) U11.6
N17009637: U1.31(OUT_D1N) U10.10
N17009639: U1.32(OUT_D1P) U10.9
N17009643: U1.26(OUT_CLKP) U11.9
N17009645: U1.25(OUT_CLKN) U11.10
N17092263: D2.1(A) R82.1

Not connected (* = marked no-connect by the designer): D1 2*; J2 20(DP_PWR)*; J5 4(7)* 5(3)* 6(8)* 7(4)* 8(9)* 9(5)*; J13 4(ID)*; R124 1*; U7 2(SUSP) 13(\\~{CTS}) 14(\\~{DSR}) 15(\\~{DCD}) 16(\\~{RI}/CP) 17(SIN/IR_SIN) 19(SOUT/IR_SOUT) 20(\\~{RTS}) 21(\\~{DTR}) 22(CLKOUT) 31(P3_1) 32(P3_0); U9 1(NC)

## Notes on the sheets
sheet 1
- Pop caps on IN_Dxx lines for DP159
  Pop 0 ohm on IN_Dxx lines for TMDS181
sheet 2
- RESET CIRCUIT
- Pop C26 and depop
  R77 if not  using
  the Reset  SW.
sheet 3
- NOTES:
  - 100-ohm differential impedance for HDMI and DP
  differential pairs.
- BLOCK
  DIAGRAM
- USB2
  CONNECTOR
- 5V
  DONGLE
- 5V to
  3.3V
  LDO
- AARDVARK
  CONNECTOR
- TUSB3410
- 3.3V to
  1.1V
  LDO
- SCL_CTL
- SDA_CTL
- DP CONNECTOR TOP
  HDMI CONNECTOR
  BOTTOM
- IN0P/N
- TMDS_D2P/N
- HDMI
  CONNECTOR
- IN1P/N
- TMDS_D1P/N
- DP159 &
  TMDS181
  (48-pin QFN)
- IN2P/N
- TMDS_D0P/N
- IN3P/N
- TMDS_CLKP/N
- AUXP/N
- DDC_SCL/SDA
sheet 4
- 3.3V BUCK REGULATOR - 4V to 17V input
- 5.0V BOOST
- 1.1V LDO REGULATOR
sheet 5
- HDMI TX
sheet 7
- Three place switches - hi, lo, no connect
  Sampled at POR
- AARDVARK
  CONNECTOR
sheet 8
- HDMI RX
- Pop 50 ohm pullups on IN_Dxx lines for DP159 thru HDMI
  No pop 50 ohm pullups on IN_Dxx lines for DP159
  No pop 50 ohm pullups on IN_Dxx lines for TMDS181
- JP 1-2 for DP159 thru HDMI
  JP 2-3 for TMDS181
  NC for DP159
- HDMI
  Connector P2
  is mounted
  on bottom of
  board
- Pop 0 ohm series on IN_Dxx lines for DP159 thru HDMI, TMDS181
  No pop 0 ohm series on IN_Dxx lines for DP159
- JP 1-2 for  DP159 thru HDMI
  JP 2-3 for TMDS181
  NC for DP159
- DisplayPort++
- Pop 0 ohm series on IN_Dxx lines for DP159
  No pop 0 ohm series on IN_Dxx lines for DP159 thru HDMI, TMDS181
- No pop for TMDS181
- No pop for DP159
